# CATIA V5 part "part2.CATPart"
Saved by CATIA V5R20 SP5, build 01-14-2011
Part number: 垫片
Bounding box of the stored display mesh (mm): x -35 to 35, y -25 to 25, z 0 to 20
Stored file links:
  E:\scc\part2.CATPart
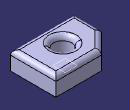
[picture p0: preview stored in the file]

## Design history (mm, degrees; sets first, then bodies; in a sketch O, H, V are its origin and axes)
Body1 (main body)
  Sketch1 on xy-plane, origin (0, 0, 0), H (1, 0, 0), V (0, 1, 0)
    line L1 (35, 25) -> (35, -25)
    line L2 (35, -25) -> (-35, -25)
    line L3 (-35, -25) -> (-35, 5)
    line L4 (-15, 25) -> (35, 25)
    line L5 (-35, 5) -> (-15, 25)
    length L1 = 50
    length L2 = 70
    length L4 = 50
    length L3 = 30
    vertical: L1 V, L3 V
    horizontal: L2 H, L4 H
    equidistance: L1 L3 O, L2 L4 O
  Pad1: profile Sketch1, direction (0, 0, 1), length 20
  Sketch2 on end face of Pad1, origin (-0.1823, -2.7421, 20), H (1, 0, 0), V (0, 1, 0)
    point P1 (0, 0)
  Hole1: placed by Sketch2, at (-0.1823, -2.7421, 20) direction (0, 0, -1), diameter 20, through (limit type 3)
  Fillet1: radius 5, on edge [face of Pad1 from Sketch1.L4 | end face of Pad1]; edge [face of Pad1 from Sketch1.L1 | end face of Pad1]; edge [face of Pad1 from Sketch1.L2 | end face of Pad1]; edge [face of Pad1 from Sketch1.L3 | end face of Pad1]; edge [face of Pad1 from Sketch1.L5 | end face of Pad1]
  Fillet2: radius 5, on edge [end face of Pad1 | face of Hole1]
